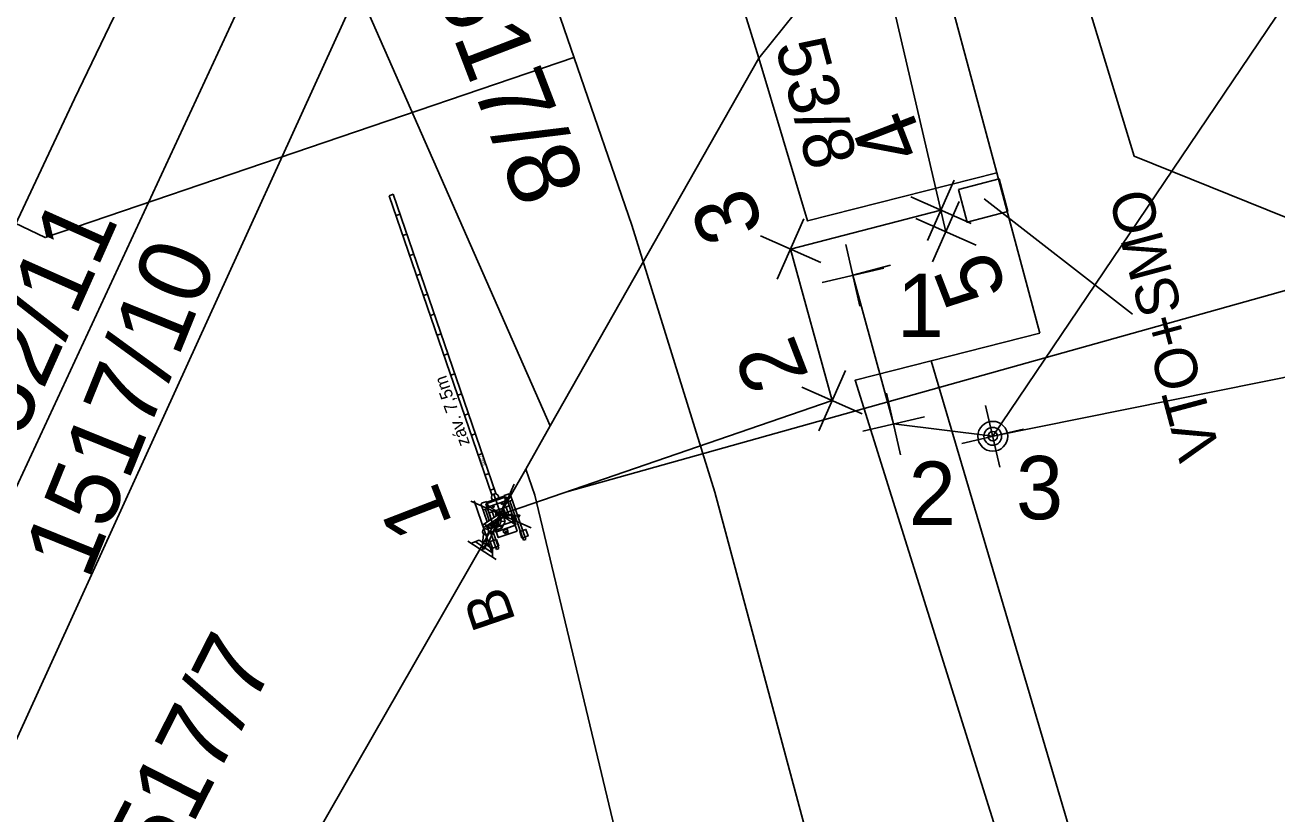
# Model space of a CAD drawing. Extents: x -553916 to -552953, y -1067470 to -1066637.
# Drawn here: x -553527.29 to -553497.63, y -1066999.25 to -1066980.55 of the extents above; entities that cross this region are included whole.
import ezdxf

# ---------------------------------------------------------------- set-up
doc = ezdxf.new("R2010")
doc.units = 0
for name, color, linetype in [('Default', 7, 'Continuous'), ('El2015-Návěst místo trati', 7, 'Continuous'), ('El2015-Ochrana podzemní', 7, 'Continuous'), ('El2015-Svršek součást', 7, 'Continuous'), ('El2015-Zabzař podzemní', 7, 'Continuous'), ('Hranice parcel', 7, 'Continuous'), ('Kolej', 7, 'Continuous'), ('Nová kabelizace', 7, 'Continuous'), ('nové prvky ZZ', 7, 'Continuous'), ('Parcelní čísla', 7, 'Continuous'), ('Propustek', 7, 'Continuous'), ('Přejezd - štěrkové lože', 7, 'Continuous'), ('trasa_NN_popisky', 7, 'Continuous'), ('trasa_NN_uzemneni', 7, 'Continuous'), ('Vrstva 1', 7, 'Continuous'), ('Vrstva 28', 7, 'Continuous')]:
    doc.layers.add(name, color=color, linetype=linetype)

# ---------------------------------------------------------------- blocks, each defined once
blk = doc.blocks.new('Křížek')
at = {"layer": 'El2015-Zabzař podzemní'}
for p, q in [((8.84, -8.84), (-8.84, 8.84)), ((8.84, -8.84), (-8.84, 8.84)), ((8.84, -8.84), (-8.84, 8.84)), ((8.84, 8.84), (-8.84, -8.84))]:
    blk.add_line(p, q, dxfattribs=at)
blk = doc.blocks.new('POINT_DISPLAY')
at = {"layer": 'Default'}
blk.add_line((0, 0), (0, 0), dxfattribs=at)
blk = doc.blocks.new('C04927')
at = {"layer": 'El2015-Svršek součást'}
for p, q in [((-0.00212, -0.00212), (0.00212, 0.00212)), ((0.00212, -0.00212), (-0.00212, 0.00212))]:
    blk.add_line(p, q, dxfattribs=at)
blk.add_blockref('POINT_DISPLAY', (0, 0), dxfattribs=at)

msp = doc.modelspace()

# ---------------------------------------------------------------- linework, layer by layer
at = {"layer": 'Hranice parcel'}
for p, q in [((-553520.52, -1066976.45), (-553530.98, -1066998.99)), ((-553519.4, -1066979.7), (-553528.66, -1067000.03))]:
    msp.add_line(p, q, dxfattribs=at)
for points in [[(-553481.25, -1066991.64), (-553501.02, -1066983.66), (-553503.13, -1066976.7), (-553485.37, -1066948.09)], [(-553533.63, -1066998.28), (-553526.12, -1066982.3), (-553521.68, -1066973.05)], [(-553515.43, -1066991.08), (-553526.38, -1067010.19), (-553539.65, -1067043.59), (-553548.33, -1067069.03)]]:
    msp.add_lwpolyline(points, dxfattribs=at)
at = {"layer": 'Kolej'}
msp.add_lwpolyline([(-553503.324, -1067065.808), (-553502.678, -1067054.027), (-553502.762, -1067041.504), (-553503.626, -1067029.057), (-553504.756, -1067019.974), (-553506.183, -1067011.388), (-553508.328, -1067001.388), (-553510.948, -1066991.622), (-553512.921, -1066985.291), (-553515.647, -1066977.347), (-553517.422, -1066972.53), (-553519.157, -1066967.95), (-553522.886, -1066958.375), (-553529.101, -1066942.549), (-553538.686, -1066918.107), (-553542.908, -1066907.329), (-553546.692, -1066897.676), (-553555.025, -1066876.441), (-553564.644, -1066851.894), (-553574.241, -1066827.427), (-553583.19, -1066804.618)], dxfattribs=at)
at = {"layer": 'Nová kabelizace'}
for p, q in [((-553505.478, -1066985.448), (-553507.017, -1066978.813)), ((-553509.157, -1066985.86), (-553505.596, -1066984.938)), ((-553508.173, -1066989.45), (-553509.157, -1066985.86)), ((-553516.02, -1066992.15), (-553508.173, -1066989.45))]:
    msp.add_line(p, q, dxfattribs=at)
at = {"layer": 'nové prvky ZZ'}
for p, q in [((-553505.18, -1066984.448), (-553504.213, -1066984.191)), ((-553504.213, -1066984.191), (-553504.008, -1066984.964)), ((-553518.666, -1066984.593), (-553518.572, -1066984.56)), ((-553516.138, -1066991.654), (-553518.572, -1066984.56)), ((-553516.232, -1066991.687), (-553518.666, -1066984.593)), ((-553504.568, -1066984.671), (-553501.059, -1066987.4)), ((-553518.504, -1066985.066), (-553518.41, -1066985.033)), ((-553518.341, -1066985.538), (-553518.248, -1066985.506)), ((-553518.179, -1066986.011), (-553518.085, -1066985.979)), ((-553518.017, -1066986.484), (-553517.923, -1066986.452)), ((-553517.855, -1066986.957), (-553517.761, -1066986.925)), ((-553517.692, -1066987.43), (-553517.598, -1066987.398)), ((-553517.53, -1066987.903), (-553517.436, -1066987.871)), ((-553517.368, -1066988.376), (-553517.274, -1066988.344)), ((-553517.205, -1066988.849), (-553517.112, -1066988.817)), ((-553517.043, -1066989.322), (-553516.949, -1066989.29)), ((-553516.881, -1066989.795), (-553516.787, -1066989.763)), ((-553516.719, -1066990.268), (-553516.625, -1066990.236)), ((-553516.556, -1066990.741), (-553516.462, -1066990.708)), ((-553516.394, -1066991.214), (-553516.3, -1066991.181)), ((-553516.176, -1066991.542), (-553516.27, -1066991.574)), ((-553516.232, -1066991.687), (-553516.138, -1066991.654)), ((-553516.02, -1066992.15), (-553516.185, -1066991.67)), ((-553515.946, -1066991.701), (-553515.827, -1066991.66)), ((-553515.941, -1066991.717), (-553515.946, -1066991.701)), ((-553515.827, -1066991.66), (-553515.798, -1066991.673)), ((-553515.798, -1066991.673), (-553515.432, -1066992.74)), ((-553516.241, -1066993.022), (-553516.65, -1066991.83)), ((-553516.476, -1066991.883), (-553516.491, -1066991.911)), ((-553516.491, -1066991.911), (-553516.348, -1066992.329)), ((-553516.357, -1066991.842), (-553516.476, -1066991.883)), ((-553515.895, -1066991.731), (-553516.377, -1066991.897)), ((-553516.377, -1066991.897), (-553516.145, -1066992.568)), ((-553515.664, -1066992.402), (-553516.377, -1066991.897)), ((-553516.352, -1066991.858), (-553516.357, -1066991.842)), ((-553516.313, -1066991.97), (-553516.302, -1066992.003)), ((-553515.899, -1066991.978), (-553516.224, -1066992.09)), ((-553516.222, -1066991.814), (-553516.065, -1066991.76)), ((-553515.895, -1066991.731), (-553516.145, -1066992.568)), ((-553515.902, -1066991.829), (-553515.891, -1066991.862)), ((-553515.894, -1066991.977), (-553515.899, -1066991.978)), ((-553515.899, -1066991.978), (-553515.833, -1066992.169)), ((-553515.895, -1066991.731), (-553515.664, -1066992.402)), ((-553515.826, -1066991.948), (-553515.895, -1066991.972)), ((-553515.895, -1066991.972), (-553515.894, -1066991.977)), ((-553515.891, -1066991.862), (-553515.772, -1066991.822)), ((-553515.748, -1066992.173), (-553515.826, -1066991.948)), ((-553515.806, -1066991.833), (-553515.488, -1066992.759)), ((-553515.772, -1066991.822), (-553515.757, -1066991.793)), ((-553516.421, -1066992.044), (-553516.45, -1066992.031)), ((-553516.433, -1066992.387), (-553516.092, -1066992.157)), ((-553516.302, -1066992.003), (-553516.421, -1066992.044)), ((-553516.393, -1066992.443), (-553516.052, -1066992.215)), ((-553516.387, -1066992.033), (-553516.297, -1066992.295)), ((-553516.3, -1066992.111), (-553516.23, -1066992.087)), ((-553516.3, -1066992.111), (-553516.248, -1066992.262)), ((-553516.23, -1066992.087), (-553516.228, -1066992.091)), ((-553516.228, -1066992.091), (-553516.224, -1066992.09)), ((-553516.224, -1066992.09), (-553516.18, -1066992.216)), ((-553516.034, -1066992.25), (-553516.178, -1066992.299)), ((-553516.039, -1066992.24), (-553516.142, -1066992.275)), ((-553516.106, -1066992.104), (-553516.125, -1066992.116)), ((-553516.125, -1066992.116), (-553516.111, -1066992.136)), ((-553516.106, -1066992.166), (-553516.113, -1066992.146)), ((-553516.111, -1066992.136), (-553516.093, -1066992.124)), ((-553516.096, -1066992.159), (-553516.102, -1066992.142)), ((-553516.06, -1066992.081), (-553516.095, -1066992.103)), ((-553516.077, -1066992.105), (-553516.089, -1066992.113)), ((-553516.038, -1066992.237), (-553516.045, -1066992.218)), ((-553516.04, -1066992.238), (-553516.024, -1066992.227)), ((-553516.027, -1066992.259), (-553516.04, -1066992.238)), ((-553516.013, -1066992.312), (-553516.035, -1066992.245)), ((-553516.01, -1066992.247), (-553516.027, -1066992.259)), ((-553516.025, -1066992.152), (-553516.015, -1066992.148)), ((-553516.022, -1066992.145), (-553516.019, -1066992.155)), ((-553516.001, -1066992.22), (-553516.012, -1066992.228)), ((-553515.97, -1066992.211), (-553516.006, -1066992.237)), ((-553515.917, -1066992.32), (-553515.958, -1066992.2)), ((-553515.792, -1066992.155), (-553515.954, -1066992.211)), ((-553515.928, -1066992.156), (-553515.951, -1066992.09)), ((-553515.789, -1066992.166), (-553515.951, -1066992.221)), ((-553515.918, -1066992.148), (-553515.939, -1066992.087)), ((-553515.897, -1066992.14), (-553515.93, -1066992.151)), ((-553515.894, -1066992.151), (-553515.92, -1066992.16)), ((-553515.888, -1066992.141), (-553515.897, -1066992.14)), ((-553515.885, -1066992.151), (-553515.894, -1066992.151)), ((-553515.878, -1066992.146), (-553515.888, -1066992.141)), ((-553515.874, -1066992.183), (-553515.885, -1066992.151)), ((-553515.872, -1066992.153), (-553515.878, -1066992.146)), ((-553515.863, -1066992.179), (-553515.872, -1066992.153)), ((-553515.774, -1066992.155), (-553515.792, -1066992.155)), ((-553515.777, -1066992.17), (-553515.789, -1066992.166)), ((-553515.726, -1066992.317), (-553515.777, -1066992.17)), ((-553515.763, -1066992.169), (-553515.774, -1066992.155)), ((-553515.713, -1066992.312), (-553515.763, -1066992.169)), ((-553515.69, -1066992.251), (-553515.712, -1066992.189)), ((-553515.682, -1066992.193), (-553515.645, -1066992.18)), ((-553515.645, -1066992.18), (-553515.636, -1066992.18)), ((-553515.636, -1066992.18), (-553515.622, -1066992.185)), ((-553515.586, -1066992.162), (-553515.597, -1066992.166)), ((-553515.584, -1066992.167), (-553515.586, -1066992.162)), ((-553515.574, -1066992.195), (-553515.586, -1066992.199)), ((-553515.577, -1066992.164), (-553515.584, -1066992.167)), ((-553515.569, -1066992.188), (-553515.577, -1066992.164)), ((-553515.569, -1066992.188), (-553515.576, -1066992.191)), ((-553515.576, -1066992.191), (-553515.574, -1066992.195)), ((-553516.364, -1066992.434), (-553516.357, -1066992.432)), ((-553516.356, -1066992.458), (-553516.364, -1066992.434)), ((-553516.359, -1066992.428), (-553516.347, -1066992.424)), ((-553516.357, -1066992.432), (-553516.359, -1066992.428)), ((-553516.356, -1066992.458), (-553516.349, -1066992.456)), ((-553516.349, -1066992.456), (-553516.347, -1066992.46)), ((-553516.347, -1066992.46), (-553516.336, -1066992.456)), ((-553516.056, -1066992.404), (-553516.342, -1066992.502)), ((-553516.324, -1066992.397), (-553516.294, -1066992.486)), ((-553516.316, -1066992.586), (-553515.995, -1066992.476)), ((-553516.308, -1066992.41), (-553516.315, -1066992.423)), ((-553516.301, -1066992.405), (-553516.308, -1066992.41)), ((-553516.264, -1066992.392), (-553516.301, -1066992.405)), ((-553516.274, -1066992.363), (-553516.238, -1066992.467)), ((-553516.265, -1066992.569), (-553516.125, -1066992.978)), ((-553516.212, -1066992.323), (-553516.218, -1066992.334)), ((-553516.183, -1066992.409), (-553516.212, -1066992.322)), ((-553516.21, -1066992.549), (-553516.069, -1066992.958)), ((-553516.16, -1066992.44), (-553516.203, -1066992.316)), ((-553515.663, -1066992.402), (-553516.145, -1066992.568)), ((-553515.72, -1066992.422), (-553516.145, -1066992.568)), ((-553516.056, -1066992.404), (-553516.013, -1066992.312)), ((-553515.995, -1066992.476), (-553516.056, -1066992.404)), ((-553515.917, -1066992.32), (-553516.013, -1066992.312)), ((-553515.995, -1066992.476), (-553515.917, -1066992.32)), ((-553515.86, -1066992.547), (-553515.857, -1066992.546)), ((-553516.132, -1066993.216), (-553516.803, -1066992.78)), ((-553516.719, -1066992.834), (-553516.533, -1066992.76)), ((-553516.22, -1066993.062), (-553516.626, -1066992.797)), ((-553516.223, -1066992.962), (-553516.533, -1066992.76)), ((-553516.467, -1066992.998), (-553516.378, -1066992.861)), ((-553516.464, -1066992.923), (-553516.429, -1066992.616)), ((-553516.385, -1066992.933), (-553516.349, -1066992.625)), ((-553515.488, -1066992.759), (-553515.432, -1066992.74)), ((-553516.414, -1066992.928), (-553516.431, -1066992.931)), ((-553516.424, -1066992.921), (-553516.422, -1066992.938)), ((-553516.216, -1066993.162), (-553516.223, -1066992.962)), ((-553516.069, -1066992.958), (-553516.125, -1066992.978))]:
    msp.add_line(p, q, dxfattribs=at)
for points in [[(-553504.008, -1066984.964), (-553504.974, -1066985.221), (-553505.18, -1066984.448)], [(-553516.232, -1066991.687), (-553516.244, -1066991.755), (-553516.223, -1066991.814)], [(-553516.138, -1066991.654), (-553516.086, -1066991.701), (-553516.066, -1066991.76)], [(-553516.202, -1066991.973), (-553516.207, -1066991.974), (-553516.22, -1066991.938), (-553516.192, -1066991.929), (-553516.179, -1066991.965), (-553516.184, -1066991.966)], [(-553516.184, -1066991.966), (-553516.182, -1066991.974), (-553516.2, -1066991.981), (-553516.202, -1066991.973)], [(-553516.004, -1066991.904), (-553516.008, -1066991.906), (-553516.021, -1066991.87), (-553515.993, -1066991.861), (-553515.981, -1066991.897), (-553515.986, -1066991.898)], [(-553515.986, -1066991.898), (-553515.983, -1066991.906), (-553516.001, -1066991.912), (-553516.004, -1066991.904)], [(-553516.109, -1066992.095), (-553516.113, -1066992.085), (-553516.151, -1066992.099), (-553516.135, -1066992.144)], [(-553516.112, -1066992.135), (-553516.145, -1066992.147), (-553516.141, -1066992.156), (-553516.092, -1066992.139)], [(-553516.085, -1066992.118), (-553516.103, -1066992.091), (-553516.111, -1066992.096), (-553516.089, -1066992.128)], [(-553516.09, -1066992.128), (-553516.107, -1066992.134)], [(-553516.016, -1066992.222), (-553515.998, -1066992.25), (-553516.005, -1066992.255), (-553516.027, -1066992.222)], [(-553515.971, -1066992.087), (-553515.934, -1066992.075), (-553515.95, -1066992.03), (-553515.988, -1066992.043), (-553515.974, -1066992.086)], [(-553515.963, -1066992.095), (-553515.923, -1066992.081), (-553515.926, -1066992.072), (-553515.971, -1066992.087), (-553515.971, -1066992.088)], [(-553515.943, -1066992.168), (-553515.942, -1066992.171), (-553515.916, -1066992.162), (-553515.919, -1066992.153), (-553515.942, -1066992.161)], [(-553515.712, -1066992.189), (-553515.72, -1066992.164), (-553515.753, -1066992.175), (-553515.726, -1066992.252)], [(-553515.69, -1066992.251), (-553515.678, -1066992.247), (-553515.7, -1066992.185), (-553515.712, -1066992.189)], [(-553515.704, -1066992.285), (-553515.682, -1066992.277), (-553515.69, -1066992.251)], [(-553515.617, -1066992.169), (-553515.621, -1066992.157), (-553515.631, -1066992.161), (-553515.609, -1066992.224), (-553515.6, -1066992.221), (-553515.603, -1066992.209)], [(-553515.597, -1066992.166), (-553515.599, -1066992.162), (-553515.617, -1066992.169)], [(-553515.603, -1066992.209), (-553515.585, -1066992.203), (-553515.586, -1066992.199)], [(-553516.347, -1066992.424), (-553516.348, -1066992.419), (-553516.33, -1066992.413)], [(-553516.316, -1066992.454), (-553516.334, -1066992.46), (-553516.336, -1066992.456)], [(-553516.33, -1066992.413), (-553516.333, -1066992.403)], [(-553516.329, -1066992.4), (-553516.324, -1066992.399), (-553516.302, -1066992.462), (-553516.312, -1066992.465), (-553516.316, -1066992.454)], [(-553516.264, -1066992.357), (-553516.229, -1066992.458), (-553516.24, -1066992.462), (-553516.274, -1066992.363)], [(-553516.218, -1066992.432), (-553516.236, -1066992.438), (-553516.257, -1066992.376), (-553516.24, -1066992.37)], [(-553516.24, -1066992.37), (-553516.248, -1066992.346)], [(-553516.244, -1066992.343), (-553516.217, -1066992.334), (-553516.191, -1066992.412)], [(-553516.21, -1066992.457), (-553516.218, -1066992.432)], [(-553516.187, -1066992.449), (-553516.199, -1066992.414), (-553516.183, -1066992.409), (-553516.171, -1066992.444)], [(-553515.857, -1066992.546), (-553515.874, -1066992.498), (-553515.968, -1066992.53), (-553515.949, -1066992.584), (-553515.909, -1066992.57)], [(-553515.905, -1066992.583), (-553515.932, -1066992.592), (-553515.928, -1066992.604), (-553515.901, -1066992.594)], [(-553515.901, -1066992.594), (-553515.849, -1066992.577), (-553515.86, -1066992.547), (-553515.911, -1066992.564), (-553515.905, -1066992.583)]]:
    msp.add_lwpolyline(points, dxfattribs=at)
for points in [[(-553515.902, -1066991.829), (-553515.941, -1066991.717), (-553516.352, -1066991.858), (-553516.313, -1066991.97)], [(-553516.121, -1066992.088), (-553516.126, -1066992.073), (-553516.148, -1066992.081), (-553516.143, -1066992.096)], [(-553515.958, -1066992.033), (-553515.963, -1066992.017), (-553515.985, -1066992.025), (-553515.98, -1066992.04)], [(-553515.922, -1066992.164), (-553515.919, -1066992.171), (-553515.936, -1066992.177), (-553515.939, -1066992.17)], [(-553515.7, -1066992.298), (-553515.717, -1066992.249), (-553515.733, -1066992.254), (-553515.716, -1066992.303)], [(-553515.658, -1066992.262), (-553515.694, -1066992.16), (-553515.707, -1066992.164), (-553515.672, -1066992.267)], [(-553515.634, -1066992.544), (-553515.713, -1066992.312), (-553516.163, -1066992.467), (-553516.083, -1066992.699)], [(-553515.521, -1066992.71), (-553515.574, -1066992.555), (-553515.428, -1066992.504), (-553515.375, -1066992.66)], [(-553516.073, -1066992.899), (-553516.126, -1066992.744), (-553516.273, -1066992.794), (-553516.219, -1066992.95)]]:
    msp.add_lwpolyline(points, close=True, dxfattribs=at)
for centre, radius in [((-553516.02, -1066992.15), 0.0725), ((-553516.383, -1066992.561), 0.0716), ((-553516.413, -1066992.415), 0.0347), ((-553516.423, -1066992.929), 0.00856)]:
    msp.add_circle(centre, radius, dxfattribs=at)
for centre, radius, start, end in [((-553516.02, -1066992.15), 0.0795, 309.387, 119.921), ((-553516.424, -1066992.927), 0.0399, 173.2567, 354.9637)]:
    msp.add_arc(centre, radius, start, end, dxfattribs=at)
at = {"layer": 'Propustek'}
for p, q in [((-553514.85, -1066990.05), (-553509.91, -1066981.33)), ((-553504.27, -1066984.05), (-553503.25, -1066987.85)), ((-553503.25, -1066987.85), (-553505.83, -1066988.51)), ((-553505.83, -1066988.51), (-553499.28, -1067010.65))]:
    msp.add_line(p, q, dxfattribs=at)
for points in [[(-553509.91, -1066981.33), (-553508.76, -1066985.19), (-553504.27, -1066984.05)], [(-553498.68, -1067074.42), (-553498.17, -1067040.43), (-553500.08, -1067020.73), (-553503.77, -1067001.28), (-553507.63, -1066988.97), (-553505.83, -1066988.51)], [(-553509.03, -1067072.35), (-553507.22, -1067040.68), (-553509.18, -1067016.9), (-553515.22, -1066991.69), (-553515.43, -1066991.08)]]:
    msp.add_lwpolyline(points, dxfattribs=at)
at = {"layer": 'Přejezd - štěrkové lože'}
msp.add_lwpolyline([(-553573.367, -1066993.961), (-553535.151, -1066981.6), (-553526.82, -1066985.587), (-553514.291, -1066981.32)], dxfattribs=at)
at = {"layer": 'trasa_NN_popisky'}
msp.add_lwpolyline([(-553456.479, -1066963.507), (-553494.623, -1066975.849), (-553504.368, -1066990.297)], dxfattribs=at)
at = {"layer": 'trasa_NN_uzemneni'}
msp.add_lwpolyline([(-553506.79, -1066986.24), (-553507.681, -1066986.481), (-553506.717, -1066990.005), (-553504.368, -1066990.297)], dxfattribs=at)
for radius in [0.354, 0.211, 0.111]:
    msp.add_circle((-553504.368, -1066990.297), radius, dxfattribs=at)
at = {"layer": 'Vrstva 1'}
for p, q in [((-553509.91, -1066981.33), (-553506.23, -1066976.75)), ((-553506.23, -1066976.75), (-553504.27, -1066984.05)), ((-553519.4, -1066979.7), (-553514.85, -1066990.05)), ((-553514.85, -1066990.05), (-553515.43, -1066991.08))]:
    msp.add_line(p, q, dxfattribs=at)
msp.add_lwpolyline([(-553513.35, -1066970.96), (-553513.02, -1066971.31), (-553509.91, -1066981.33)], dxfattribs=at)
at = {"layer": 'Vrstva 28'}
for p, q in [((-553261.015, -1066920.514), (-553514.461, -1066991.614)), ((-553504.368, -1066990.297), (-553260.214, -1066940.912))]:
    msp.add_line(p, q, dxfattribs=at)

# ---------------------------------------------------------------- block references
at = {"layer": 'El2015-Ochrana podzemní', "xscale": 0.06250000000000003, "yscale": 0.0625, "rotation": 111.13806774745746}
for p in [(-553505.596, -1066984.938), (-553505.478, -1066985.448), (-553509.157, -1066985.86), (-553508.173, -1066989.45), (-553516.02, -1066992.15)]:
    msp.add_blockref('Křížek', p, dxfattribs=at)
at = {"layer": 'El2015-Svršek součást', "xscale": 249.9999999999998, "yscale": 249.99999999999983, "rotation": 147.9190601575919}
for p in [(-553507.681, -1066986.481), (-553506.717, -1066990.005), (-553504.368, -1066990.297)]:
    msp.add_blockref('C04927', p, dxfattribs=at)

# ---------------------------------------------------------------- texts
at = {"layer": 'Default'}
for s, p in [('4', (-553505.925, -1066983.499)), ('3', (-553509.768, -1066985.352)), ('5', (-553504.007, -1066986.854)), ('2', (-553508.711, -1066988.877)), ('1', (-553517.156, -1066992.373))]:
    msp.add_text(s, height=1.5, rotation=111.1381, dxfattribs=at).set_placement(p)
at = {"layer": 'El2015-Návěst místo trati'}
for s, p in [('1', (-553506.64, -1066987.945)), ('3', (-553503.816, -1066992.264)), ('2', (-553506.358, -1066992.397))]:
    msp.add_text(s, height=1.5, dxfattribs=at).set_placement(p)
at = {"layer": 'nové prvky ZZ'}
for s, height, rotation, p in [('VTO+SMO', 1, 104.9376, (-553498.965, -1066990.707)), ('záv. 7,5m', 0.3, 109.138, (-553516.752, -1066990.475)), ('7,50m', 0.0646, 288.9398, (-553516.526, -1066990.764)), ('265', 0.025, 288.9398, (-553515.996, -1066992.119)), ('B', 1.025, 108.8917, (-553515.663, -1066994.668))]:
    msp.add_text(s, height=height, rotation=rotation, dxfattribs=at).set_placement(p)
at = {"layer": 'Parcelní čísla'}
for s, rotation, p in [('1652/11', 66, (-553528.413, -1066992.687)), ('1517/10', 68, (-553525.803, -1066993.733)), ('1517/7', 63, (-553524.481, -1067001.782))]:
    msp.add_text(s, height=1.7, rotation=rotation, dxfattribs=at).set_placement(p)
at = {"layer": 'Vrstva 1'}
for s, height, rotation, p in [('1517/8', 1.7, 290.9878, (-553518.068, -1066978.458)), ('53/8', 1.2, 285, (-553509.531, -1066981.03))]:
    msp.add_text(s, height=height, rotation=rotation, dxfattribs=at).set_placement(p)

doc.saveas('drawing.dxf')
